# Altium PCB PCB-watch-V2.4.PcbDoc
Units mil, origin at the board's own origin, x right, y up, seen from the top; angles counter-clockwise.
Board outline 1043.31 x 1259.84 mil, 4 copper layers (Top Layer, GND, POWER, Bottom Layer), stack 23.756 mil thick; 96 components, 97 nets, 405 pads, 178 vias.
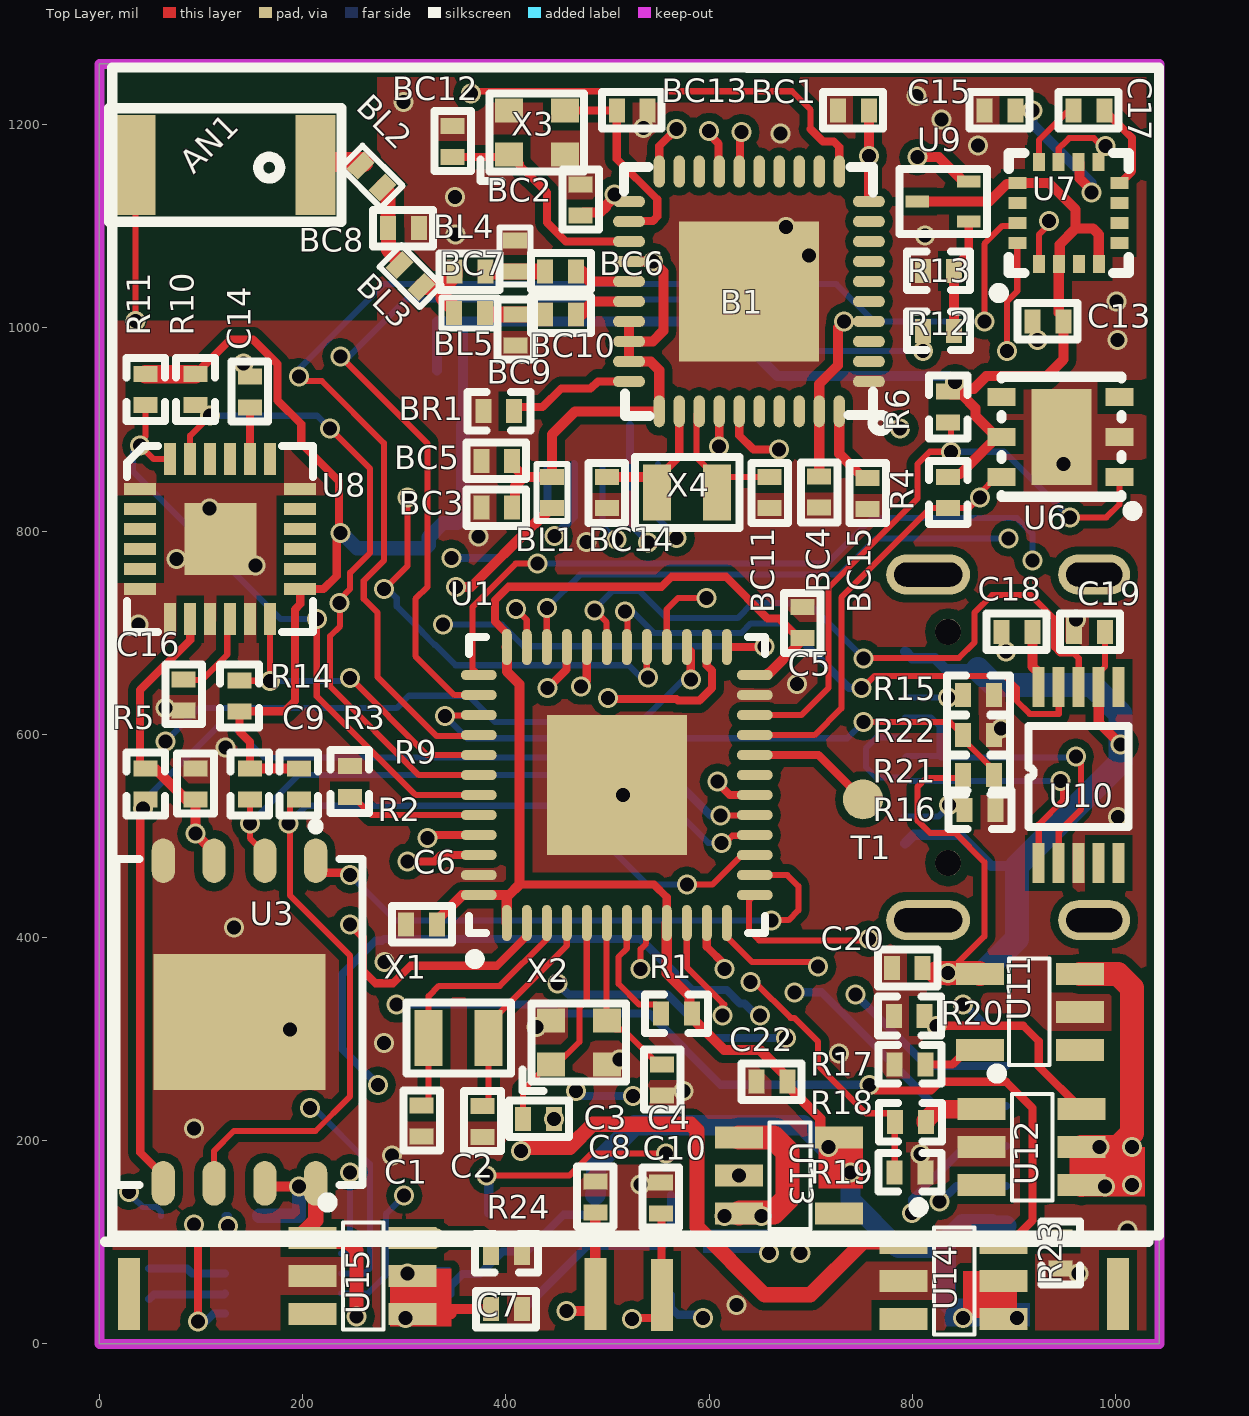
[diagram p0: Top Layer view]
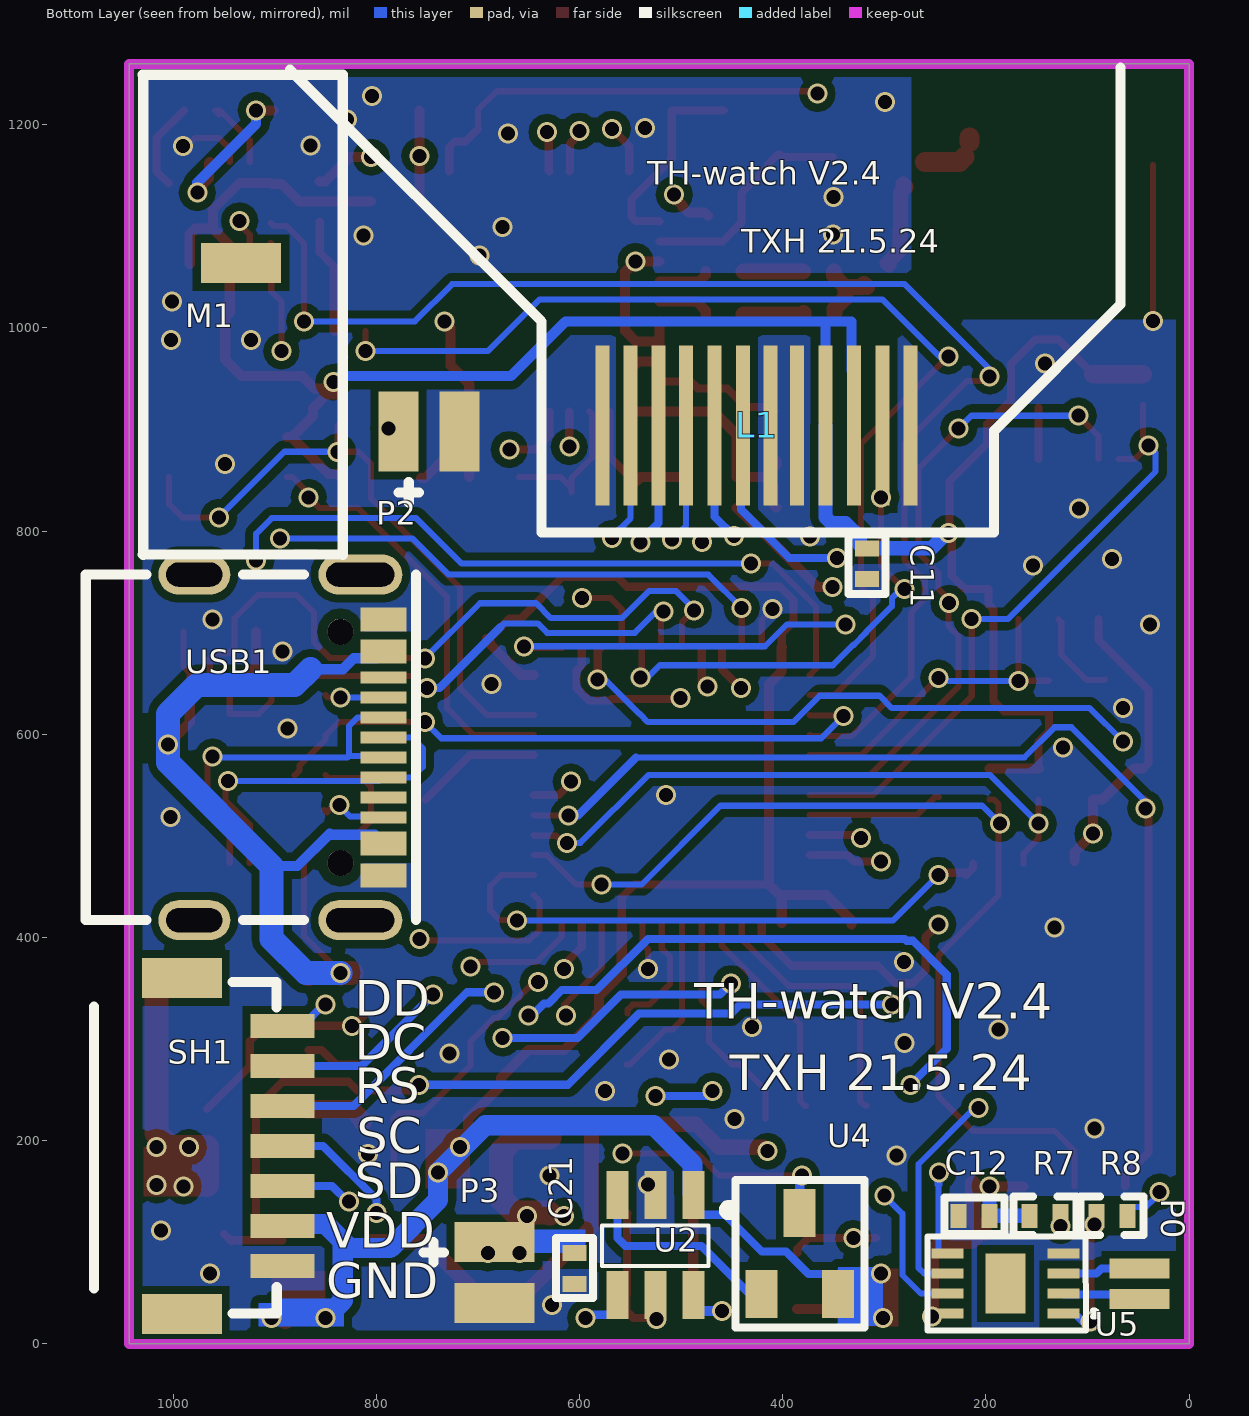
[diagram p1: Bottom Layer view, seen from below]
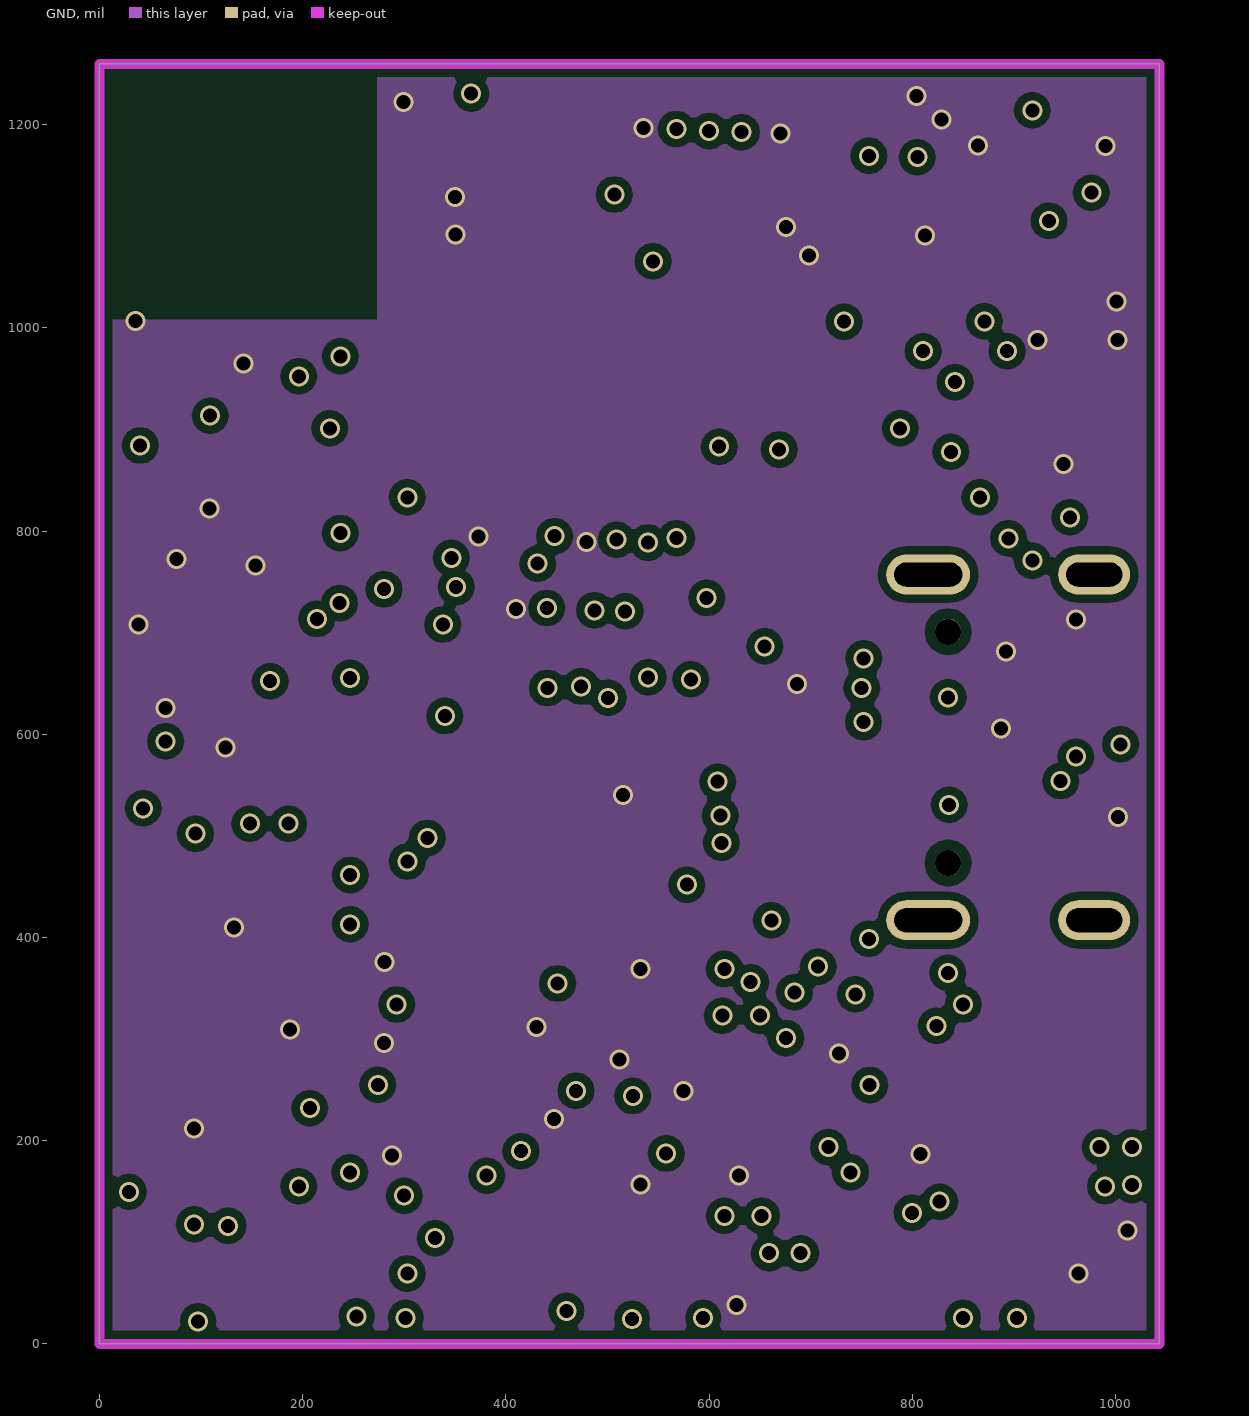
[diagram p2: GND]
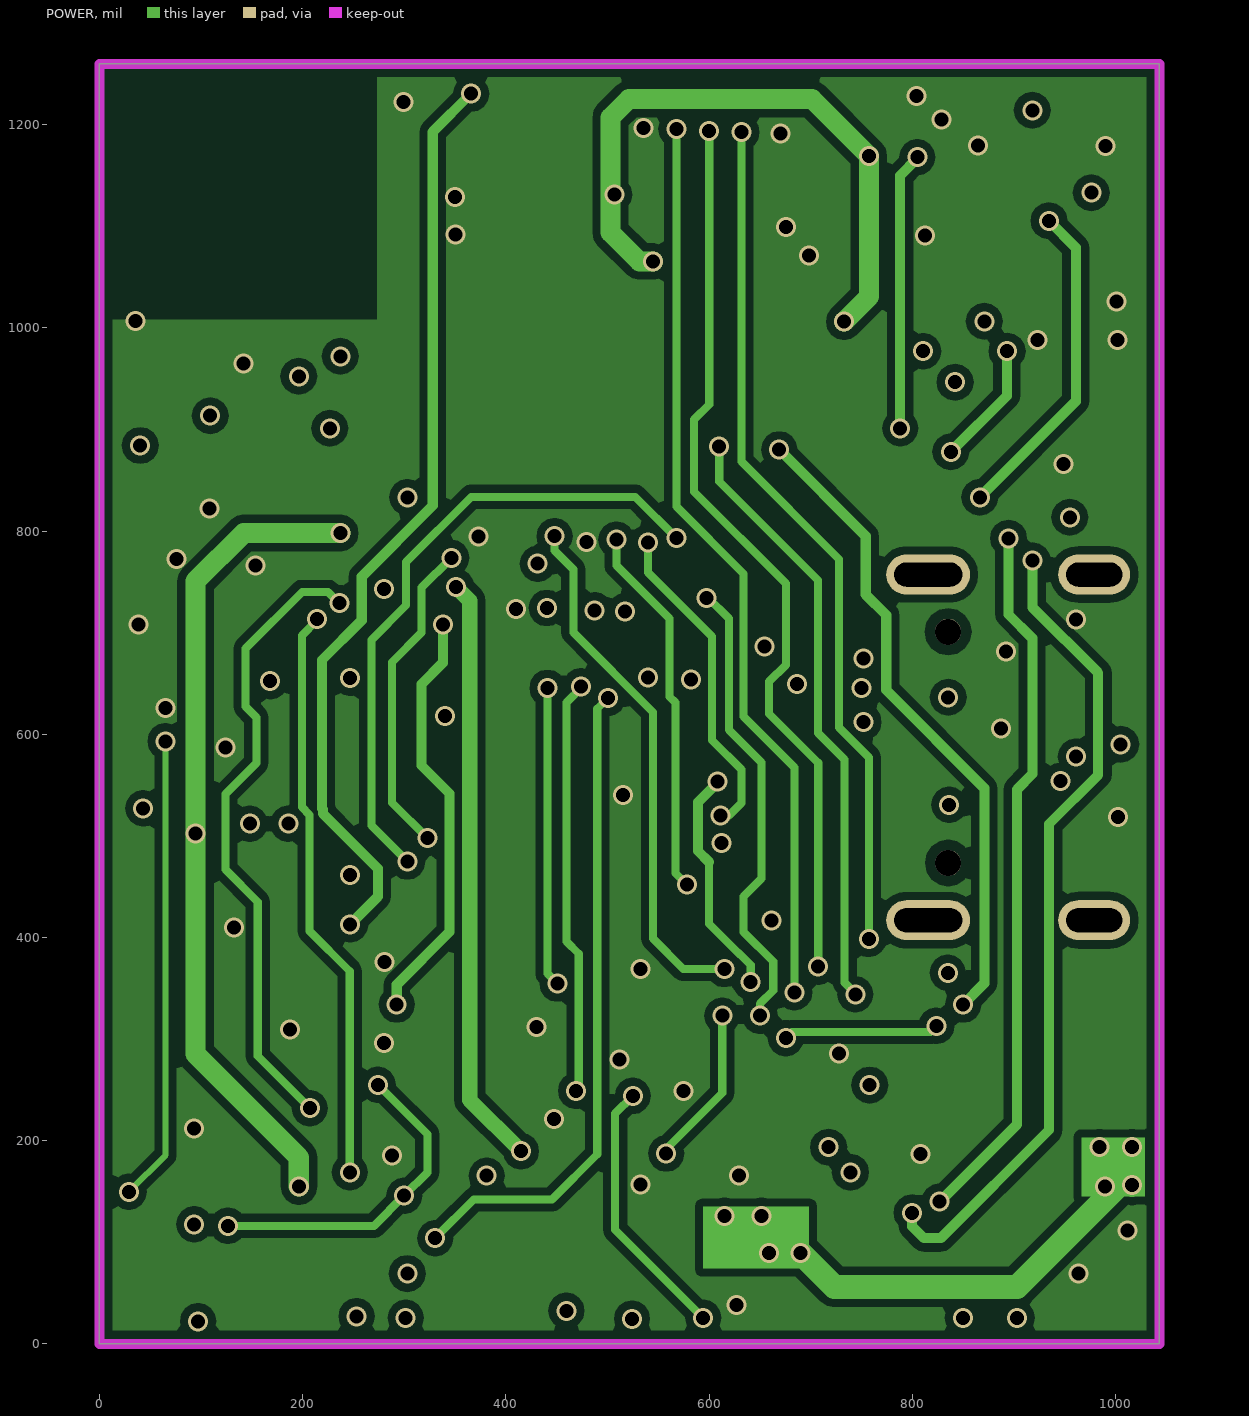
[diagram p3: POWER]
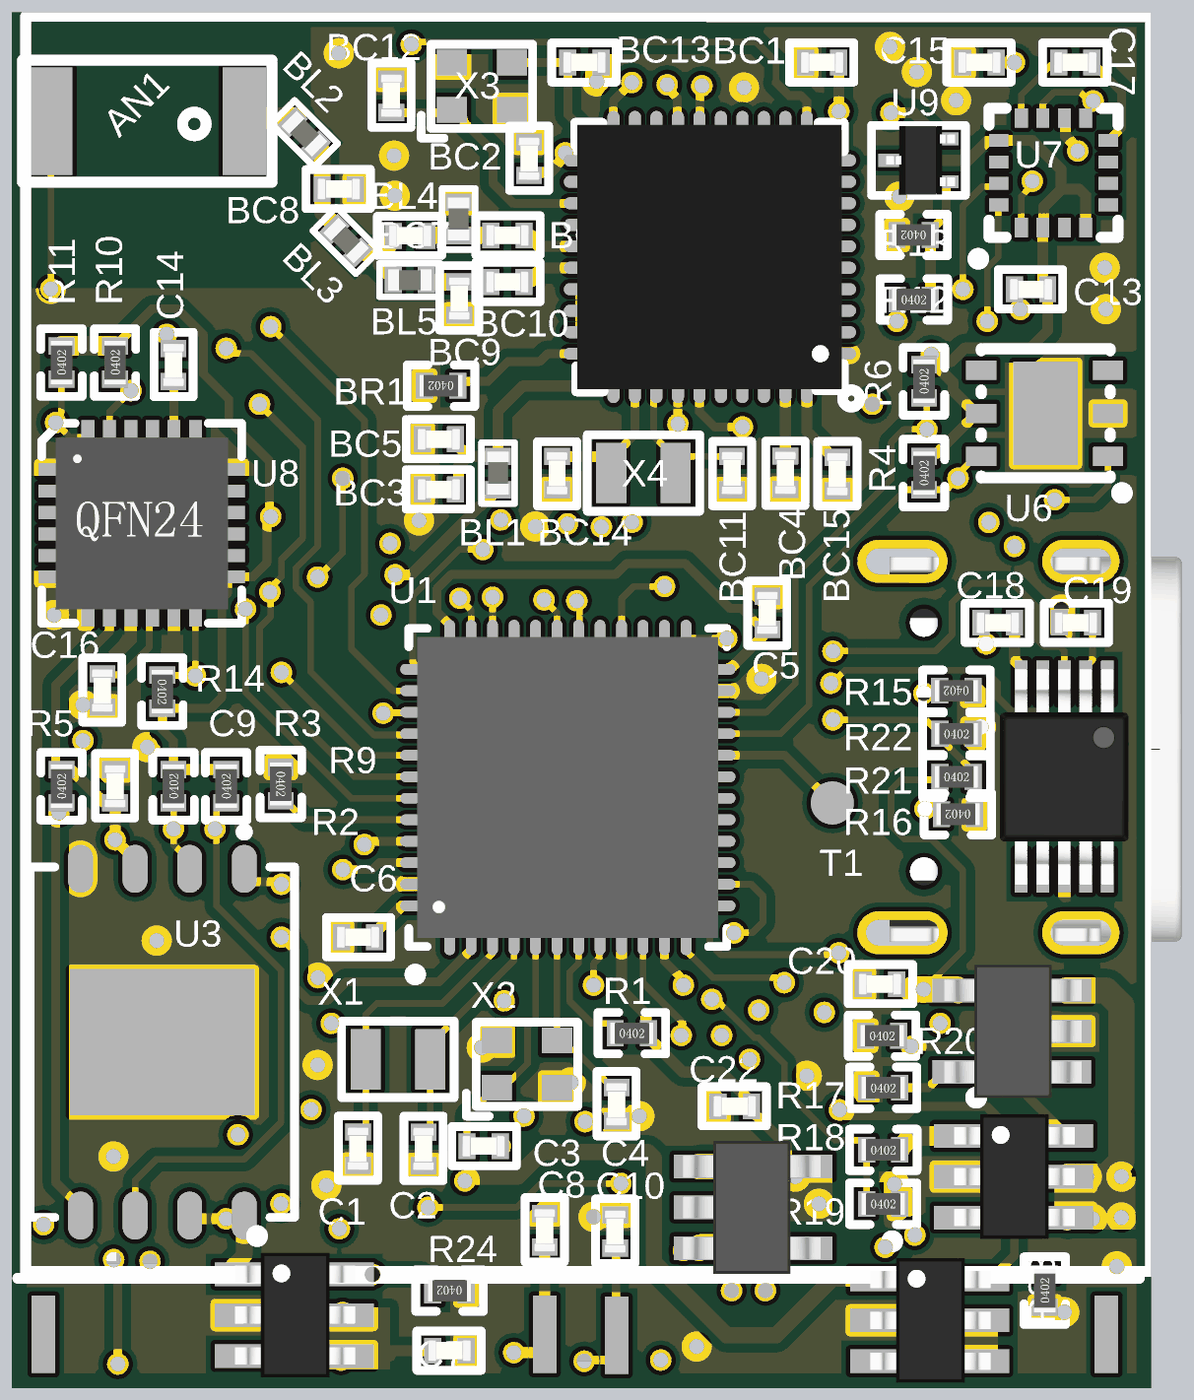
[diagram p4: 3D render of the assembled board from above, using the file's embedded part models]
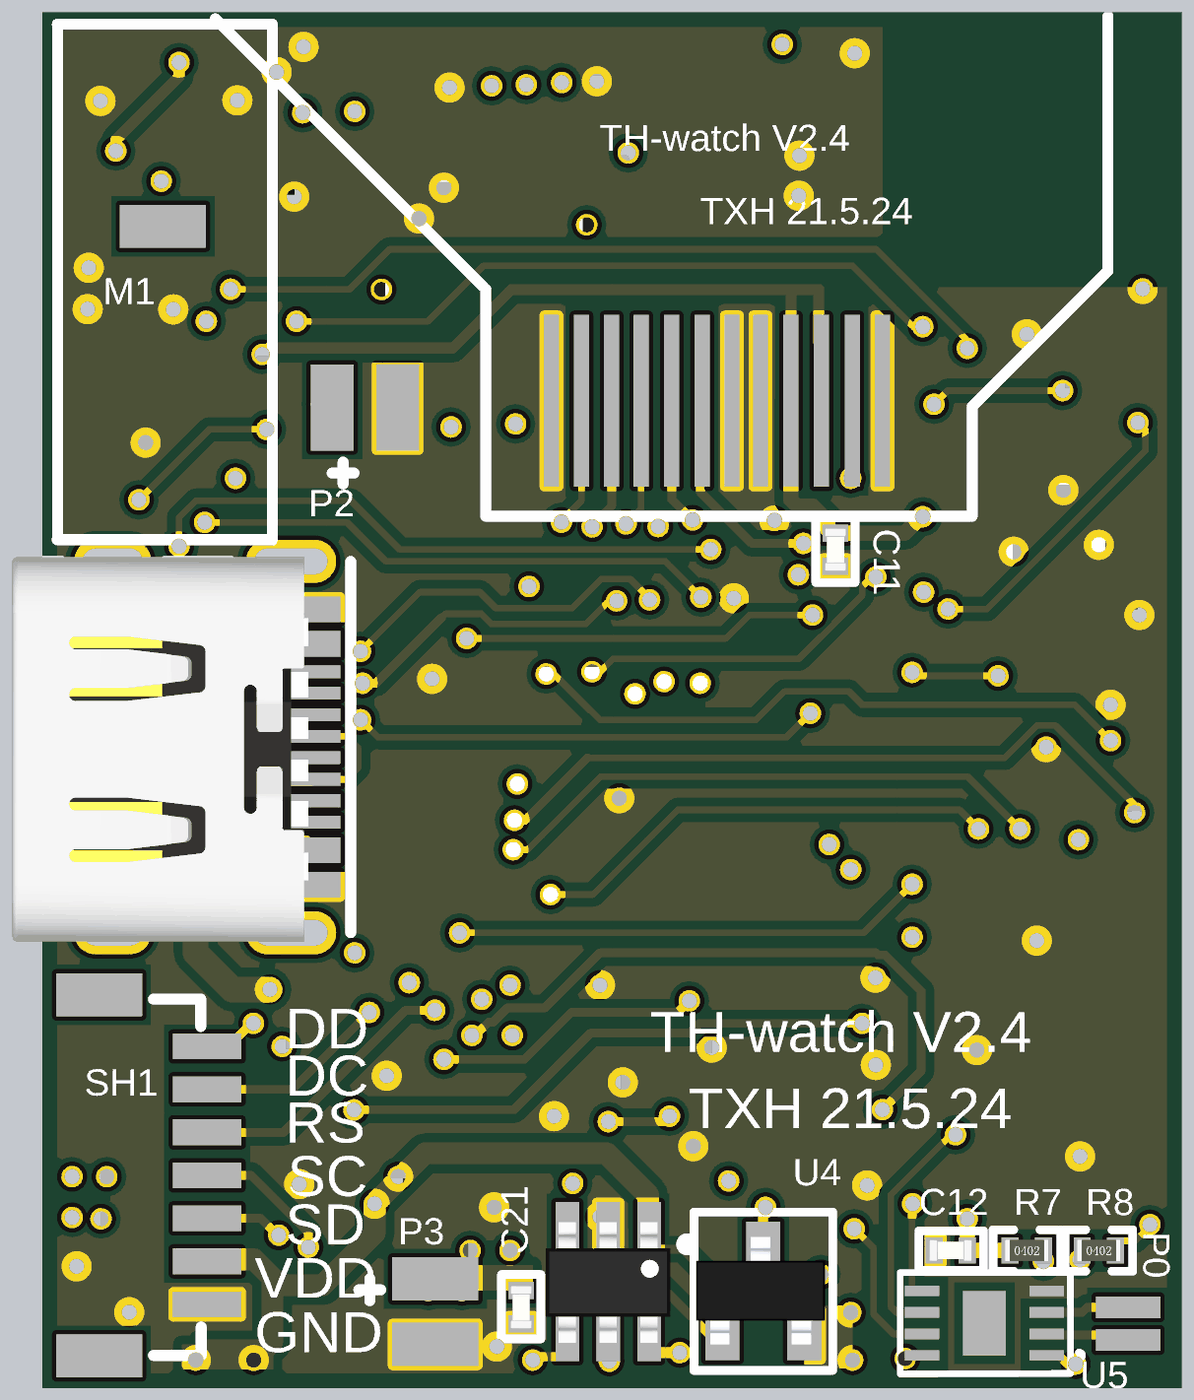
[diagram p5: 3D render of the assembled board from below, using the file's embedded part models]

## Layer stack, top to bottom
Top Solder: solder mask 0.4, Solder Resist, Dk 3.5
Top Layer: signal copper 1.4
Dielectric 2: prepreg 2.8, PP-006, Dk 4.1
GND: signal copper 1.378
Dielectric 1: dielectric 12.6, FR-4, Dk 4.8
POWER: signal copper 1.378
Dielectric 3: prepreg 2.8, PP-006, Dk 4.1
Bottom Layer: signal copper 1.4
Bottom Solder: solder mask 0.4, Solder Resist, Dk 3.5

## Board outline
0,0 0,1259.84 1043.31,1259.84 1043.31,0

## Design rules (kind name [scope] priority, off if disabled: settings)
Clearance [All] p1: gap=8 ignorepadtopadclearanceinfootprint=TRUE except(4: Arc-Arc Arc-Track Arc-SMDPad Arc-THPad Arc-Via Track-Track Track-SMDPad Track-THPad Track-Via SMDPad-SMDPad SMDPad-THPad SMDPad-Via THPad-THPad THPad-Via Via-Via; 10: Arc-Text Arc-Hole Track-Text Track-Hole SMDPad-Text SMDPad-Hole THPad-Text THPad-Hole Via-Text Via-Hole Fill-Text Fill-Hole Poly-Text Poly-Hole Region-Text Region-Hole Text-Text Text-Hole)
DiffPairsRouting [All] p1: maxlimit=10 minlimit=5.91 mostfreqgap=10 toplayer_minwidth=15 toplayer_maxwidth=15 toplayer_prefwidth=15 midlayer1_minwidth=15 midlayer1_maxwidth=15 midlayer1_prefwidth=15 midlayer2_minwidth=15 midlayer2_maxwidth=15 midlayer2_prefwidth=15 bottomlayer_minwidth=15 bottomlayer_maxwidth=15 bottomlayer_prefwidth=15 maxuncoupledlength=500
HoleToHoleClearance [All] p1: gap=5.91 allowstackedmicrovias=TRUE
MinimumSolderMaskSliver [All] p1: minsoldermaskwidth=0.39
PlaneConnect [All] p1: planeconnectstyle=Relief reliefexpansion=20 reliefentries=4 reliefconductorwidth=19.68 reliefairgap=10
PolygonConnect [All] p1: connectstyle=Direct reliefconductorwidth=15.75 reliefentries=4 polygonreliefangle="90 Angle" airgapwidth=5.91
RoutingVias [All] p1: holewidth=118.11 width=118.11 viastyle="Through Hole" minholewidth=9.84 minwidth=13.78 maxholewidth=118.11 maxwidth=118.11
SilkToSilkClearance [All] p1: silktosilkclearance=0
SilkToSolderMaskClearance [IsPad] p1: minsilkscreentomaskgap=0 clearancetoexposedcopper=TRUE
SolderMaskExpansion [All] p1: expansion=4
Width [All] p1: maxlimit=39.37 minlimit=3 preferedwidth=6
24 further rules are at their usual default settings.

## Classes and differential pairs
component class 04-POWERV2.4: C18 C19 C20 C21 C22 P3 R15 R16 R17 R18 R19 R20 R21 R22 R23 R24 U10 U11 U12 U13 U14 USB1
component class 03-PeripheralPart-V2.4: 1 C7 C8 C9 C10 C11 C12 C13 C14 C15 C16 C17 L1 M1 P0 P2 R3 R4 R5 R6 R7 R8 R9 R10 R11 R12 R13 R14 U2 U3 U4 U5 U6 U7 U8 U9
component class 02-bluetooth-V2.4: AN1 B1 BC1 BC2 BC3 BC4 BC5 BC6 BC7 BC8 BC9 BC10 BC11 BC12 BC13 BC14 BC15 BL1 BL2 BL3 BL4 BL5 BR1 X3 X4
component class 01-MCU-V2.4: C1 C2 C3 C4 C5 C6 R1 R2 SH1 T1 U1 X1 X2

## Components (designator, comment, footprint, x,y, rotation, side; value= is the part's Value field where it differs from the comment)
AN1 "AN9520-245" AN-5120 212.79,1160.24 r180 top
B1 "CC2541" QFN40-CC254X 639.28,1035.84 r90 top
BC1 "100nF" CC1005-0402 742.09,1214 r180 top
BC2 "100nF" CC1005-0402 473.67,1125.87 r90 top
BC3 "220nF" CC1005-0402 391,823 r180 top
BC4 "100nF" CC1005-0402 708.43,838.24 r270 top
BC5 "10uF" CC1005-0402 391,869 r180 top
BC6 "18pF" CC1005-0402 453.87,1055.63 r0 top
BC7 "1pF" CC1005-0402 364.68,1055.2 r180 top
BC8 "1pF" CC1005-0402 299.34,1098.11 r180 top
BC9 "1pF" CC1005-0402 409.69,997.84 r90 top
BC10 "18pF" CC1005-0402 453.76,1013 r0 top
BC11 "15pF" CC1005-0402 659.56,838 r270 top
BC12 "27pF" CC1005-0402 347.56,1183.57 r90 top
BC13 "27pF" CC1005-0402 524.39,1214 r180 top
BC14 "15pF" CC1005-0402 499.32,837.83 r270 top
BC15 "100pF" CC1005-0402 756,836.96 r90 top
BL1 "2nH" Inductor-0402 445.24,838 r270 top
BL2 "1nH" Inductor-0402 267.87,1148.81 r315 top
BL3 "1nH" Inductor-0402 306.15,1050.96 r315 top
BL4 "2nH" Inductor-0402 409.11,1070.64 r270 top
BL5 "2nH" Inductor-0402 364.41,1014.72 r0 top
BR1 "56KR" CR1005-0402 393,918 r180 top
C1 "15pF" CC1005-0402 317,219.24 r90 top
C2 "15pF" CC1005-0402 377,219 r90 top
C3 "27pF" CC1005-0402 432,221.52 r0 top
C4 "27pF" CC1005-0402 553.81,259.88 r90 top
C5 "100nF" CC1005-0402 691.89,710.02 r270 top
C6 "100nF" CC1005-0402 317.01,412.91 r0 top
C7 "100NF" CC1005-0402 400.81,34.2 r180 top
C8 "1pF" CC1005-0402 488,144.46 r90 top
C9 "100nF" CC1005-0402 94.47,551.13 r90 top
C10 "1pF" CC1005-0402 552.54,143.34 r90 top
C11 "100nF" CC1005-0402 317.01,767.81 r270 bottom
C12 "100nF" CC1005-0402 211.51,126 r180 bottom
C13 "100nF" CC1005-0402 933.45,1006.31 r180 top
C14 "2.2uF" CC1005-0402 148,937 r90 top
C15 "4.7uF" CC1005-0402 886.2,1214 r180 top
C16 "100NF" CC1005-0402 82.79,638.83 r90 top
C17 "0.22uF" CC1005-0402 974,1214 r180 top
C18 "100nF" CC1005-0402 902.98,700.86 r180 top
C19 "100nF" CC1005-0402 974.51,700.86 r0 top
C20 "10uF" CC1005-0402 795.03,369.91 r0 top
C21 "10uF" CC1005-0402 604.89,74 r90 bottom
C22 "10uF" CC1005-0402 662,258 r180 top
L1 "TFT LED" LCD-1.3-(2) 274,904.07 r180 top locked
M1 "motor" motor 833,1249 r0 bottom
P0 "power" POWER2 49,74 r270 bottom
P2 "power" POWER-3.7V 793,848 r180 bottom
P3 "power" POWER-3.7V 733.57,115 r270 bottom
R1 "10K" CR1005-0402 567.78,325 r0 top
R2 "10K" CR1005-0402 246.34,553.31 r270 top
R3 "47K" CR1005-0402 148,551.13 r90 top
R4 "10K" CR1005-0402 835.3,838 r90 top
R5 "47K" CR1005-0402 45.39,551.13 r90 top
R6 "10K" CR1005-0402 835.3,922 r90 top
R7 "4.7K" CR1005-0402 141.72,126 r180 bottom
R8 "1K" CR1005-0402 75.78,126 r180 bottom
R9 "47K" CR1005-0402 196.27,551.13 r90 top
R10 "10K" CR1005-0402 94.47,939.22 r90 top
R11 "10K" CR1005-0402 45.39,939.22 r90 top
R12 "1K" CR1005-0402 826,997 r0 top
R13 "10K" CR1005-0402 825.86,1056 r180 top
R14 "10K" CR1005-0402 137.79,637.83 r270 top
R15 "1.5K" CR1005-0402 865,638.58 r180 top
R16 "1.5K" CR1005-0402 866.53,525.6 r180 top
R17 "2KR" CR1005-0402 797.97,275 r0 top
R18 "10K" CR1005-0402 798.03,218.13 r0 top
R19 "10K" CR1005-0402 797.97,168.73 r0 top
R20 "10K" CR1005-0402 797.03,322.72 r0 top
R21 "10K" CR1005-0402 865.14,559.84 r0 top
R22 "10K" CR1005-0402 865.14,599.21 r0 top
R23 "10K" CR1005-0402 946,89.24 r90 top
R24 "10K" CR1005-0402 400.81,89.24 r180 top
SH1 "SH1.0-7P" SH1.0-7P 925.65,234.18 r270 bottom
T1 "测试点" 测试点 751.44,535.86 r0 top
U1 "STM32L431CCU6" STM32-UFQFPN48_N 509.16,550 r90 top locked
U2 "BS812A-1" SOT23-6 522.81,96.65 r0 bottom
U3 "W25Q64JVEIQ" WSON-8_L8.0-W6.10-P1.27-TL-EP 137.79,316.73 r270 top
U4 "SI2305" SOT-23 420.57,49.15 r180 bottom
U5 "ST25DV04k" UFDFPN8 180.59,59.4 r0 bottom
U6 "SI7020" DFN-6 945.84,892.64 r90 top
U7 "HMC5883L" LPCC-16_L3.0-W3.0-P0.50-BL 954,1113 r0 top
U8 "MPU6050" "QFN24 - duplicate" 118.82,792.01 r0 top
U9 "MMBT3904TT1G" SOT-416 830.3,1124.43 r0 top
U10 "CH340E" MSOP-10 924.47,473.3 r90 top
U11 "TP4054" SOT23-5 964.95,364.33 r270 top
U12 "TPS22860" SOT23-6 918.22,196 r270 top
U13 "TPS709" SOT23-5 629.69,127.91 r90 top
U14 "TPS22860" SOT23-6 841.23,64.39 r270 top
U15 "TPS22860" SOT23-6 259.44,69.2 r270 top
USB1 "Tpye-c 16P" "TYPE-C 16P" 835.3,473.3 r270 bottom locked
X1 "32.768Khz" XTAL-2012 383.06,301 r180 top
X2 "32Mhz" XTAL-2016 444.2,275 r0 top
X3 "32Mhz" XTAL-2016 402.88,1170.69 r0 top
X4 "32.768Khz" XTAL-2012 548.94,838 r0 top

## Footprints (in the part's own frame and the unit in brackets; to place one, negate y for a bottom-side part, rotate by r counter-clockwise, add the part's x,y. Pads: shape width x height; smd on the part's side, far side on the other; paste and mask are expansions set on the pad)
AN-5120 [mm]
  rect 1x2.5 smd: 1(0,0) 2(4.5,0)
  silkscreen extent -0.65,-1.42 5.16,1.42, body extent -0.32,-1.03 4.77,1.03, height 1.2
CC1005-0402 [mm]
  rect 0.4x0.6 smd: 1(-0.387,0) 2(0.387,0)
  silkscreen extent -0.74,-0.46 0.76,0.46, body extent -0.5,-0.25 0.5,0.25, height 0.3
CR1005-0402 [mm]
  rect 0.4x0.6 smd: 1(-0.387,0) 2(0.387,0)
  silkscreen extent -0.79,-0.48 0.79,0.48, body extent -0.5,-0.25 0.5,0.25, height 0.35
DFN-6 [mm]
  rect 0.45x0.701 smd: 1(-1.001,-1.476) 2(0,-1.476) 3(1.001,-1.476) 4(1.001,1.476) 5(0,1.476) 6(-1.001,1.476)
  rect 2.4x1.5 smd: 7(0,-0.025)
  silkscreen extent -1.95,-1.9 1.5,1.47, body extent -1.52,-1.55 1.5,1.47, height 1
Inductor-0402 [mm]
  rect 0.4x0.6 smd: 1(-0.387,0) 2(0.387,0)
  silkscreen extent -0.71,-0.39 0.71,0.39, body extent -0.5,-0.25 0.5,0.25, height 0.25
LCD-1.3-(2) [mm]
  rect 0.35x4 smd far side: 1(0,0) 2(-0.7,0) 3(-1.419,0) 4(-2.128,0) 5(-2.838,0) 6(-3.5,0) 7(-4.193,0) 8(-4.902,0) 9(-5.612,0) 10(-6.3,0) 11(-7,0) 12(-7.7,0)
  silkscreen extent -19.53,-8.94 6.64,20.25, body extent -19.52,-8.94 6.67,20.21, height 2.32
LPCC-16_L3.0-W3.0-P0.50-BL [mm]
  rect 0.3x0.45 smd: 1(-0.749,-1.275) 2(-0.249,-1.275) 3(0.251,-1.275) 4(0.751,-1.275) 9(0.75,1.275) 10(0.25,1.275) 11(-0.25,1.275) 12(-0.749,1.275)
  rect 0.45x0.3 smd: 5(1.275,-0.748) 6(1.275,-0.248) 7(1.275,0.252) 8(1.275,0.752) 13(-1.275,0.752) 14(-1.275,0.252) 15(-1.275,-0.248) 16(-1.275,-0.748)
  silkscreen extent -1.87,-2.12 1.5,1.5, body extent -1.42,-1.48 1.42,1.42, height 0.9
motor [mm]
  rect 2x1 smd: 3(2.54,4.699)
  silkscreen extent 0,0 5,12, body extent 0,0.03 4.95,11.96, height 4.9
MSOP-10 [mm]
  rect 1x0.3 smd: 1(0,0) 2(0,-0.5) 3(0,-1) 4(0,-1.5) 5(0,-2) 6(4.403,-2) 7(4.403,-1.5) 8(4.403,-1) 9(4.403,-0.5) 10(4.403,0)
  silkscreen extent 0.9,-2.25 3.42,0.25, body extent -0.32,-2.5 4.71,0.5, height 1.05
POWER2 [mm]
  rect 0.5x1.5 smd: 1(0,0) 2(0.762,0)
POWER-3.7V [mm]
  rect 1x2 smd: 1(0.381,1.27) 2(1.905,1.27)
  silkscreen extent 0.38,-0.51 0.89,0
"QFN24 - duplicate" [mm]
  rect 0.8x0.3 smd: 1(-2,1.25) 2(-2,0.75) 3(-2,0.25) 4(-2,-0.25) 5(-2,-0.75) 6(-2,-1.25) 13(2,-1.25) 14(2,-0.75) 15(2,-0.25) 16(2,0.25) 17(2,0.75) 18(2,1.25)
  rect 1.8x1.8 smd: 1(0.005,0)
  rect 0.3x0.8 smd: 7(-1.25,-2) 8(-0.75,-2) 9(-0.25,-2) 10(0.25,-2) 11(0.75,-2) 12(1.25,-2) 19(1.25,2) 20(0.75,2) 21(0.25,2) 22(-0.25,2) 23(-0.75,2) 24(-1.25,2)
  silkscreen extent -2.32,-2.32 2.32,2.32, body extent -2,-2 2.01,2, height 0.9
QFN40-CC254X [mm]
  oval 0.28x0.8 smd: 1(-2.25,-2.998) 2(-1.75,-2.998) 3(-1.25,-2.998) 4(-0.75,-2.998) 5(-0.25,-2.998) 6(0.25,-2.998) 7(0.75,-2.998) 8(1.25,-2.998) 9(1.75,-2.998) 10(2.25,-2.998) 21(2.246,2.996) 22(1.75,2.998) 23(1.25,2.998) 24(0.75,2.998) 25(0.25,2.998) 26(-0.25,2.998) 27(-0.75,2.998) 28(-1.25,2.998) 29(-1.75,2.998) 30(-2.25,2.998)
  oval 0.8x0.28 smd: 11(2.998,-2.256) 12(2.998,-1.756) 13(2.998,-1.256) 14(2.998,-0.756) 15(2.998,-0.256) 16(2.998,0.244) 17(2.998,0.744) 18(2.998,1.244) 19(2.998,1.744) 20(2.998,2.244) 31(-2.998,2.244) 32(-2.998,1.744) 33(-2.998,1.244) 34(-2.998,0.744) 35(-2.998,0.244) 36(-2.998,-0.256) 37(-2.998,-0.756) 38(-2.998,-1.256) 39(-2.998,-1.756) 40(-2.998,-2.256)
  rect 3.5x3.5 smd: 41(0,0)
  silkscreen extent -3.49,-3.49 3.11,3.12, body extent -3.08,-3.07 3.07,3.08, height 1.08
SH1.0-7P [mm]
  rect 0.6x1.6 smd: 1(-2,0.844) 2(-1,0.844) 3(0,0.844) 4(1,0.844) 5(2,0.844) 6(3,0.844) 7(4,0.844)
  rect 1x2 smd: 8(-3.2,-1.67) 9(5.2,-1.67)
  silkscreen extent -3.1,-3.87 5.19,0.7, body extent -3.15,-3.89 5.18,0.69, height 3
SOT23-5 [mm] "适用于MIC5205"
  rect 0.55x1.2 smd: 1(1.905,0) 2(0.955,0) 3(0.005,0) 4(0.005,-2.5) 5(1.905,-2.5)
  silkscreen extent -0.38,-1.78 2.29,-0.76, body extent -0.6,-2.82 2.5,0.38, height 1.45
SOT23-6 [mm]
  rect 0.55x1.2 smd: 1(-0.889,-1.27) 2(0.061,-1.27) 3(1.011,-1.27) 4(1.011,1.23) 5(0.061,1.23) 6(-0.889,1.23)
  silkscreen extent -1.9,-1.02 1.4,0.51, body extent -1.39,-1.4 1.51,1.4, height 1.45
SOT-23 [mm]
  rect 0.8x1.2 smd: 1(0,0) 2(1.905,0) 3(0.95,2.02)
  silkscreen extent -0.66,-0.84 2.57,2.84, body extent -0.61,-0.23 2.39,2.27, height 1.05
SOT-416 [mm]
  rect 0.585x0.301 smd: 1(0.642,-0.5) 2(0.642,0.5) 3(-0.642,0)
  silkscreen extent -1.09,-0.81 1.09,0.81, body extent -0.75,-0.8 0.85,0.8, height 0.78
STM32-UFQFPN48_N [mm] "QFN, 48-Leads, Body 7.1x7.1mm, Pitch 0.5mm, Thermal Pad 5.6x5.6mm, IPC Medium Density"
  oval 0.9x0.25 smd: 1(-3.45,2.75) 2(-3.45,2.25) 3(-3.45,1.75) 4(-3.45,1.25) 5(-3.45,0.75) 6(-3.45,0.25) 7(-3.45,-0.25) 8(-3.45,-0.75) 9(-3.45,-1.25) 10(-3.45,-1.75) 11(-3.45,-2.25) 12(-3.45,-2.75) 25(3.45,-2.75) 26(3.45,-2.25) 27(3.45,-1.75) 28(3.45,-1.25) 29(3.45,-0.75) 30(3.45,-0.25) 31(3.45,0.25) 32(3.45,0.75) 33(3.45,1.25) 34(3.45,1.75) 35(3.45,2.25) 36(3.45,2.75)
  oval 0.25x0.9 smd: 13(-2.75,-3.45) 14(-2.25,-3.45) 15(-1.75,-3.45) 16(-1.25,-3.45) 17(-0.75,-3.45) 18(-0.25,-3.45) 19(0.25,-3.45) 20(0.75,-3.45) 21(1.25,-3.45) 22(1.75,-3.45) 23(2.25,-3.45) 24(2.75,-3.45) 37(2.75,3.45) 38(2.25,3.45) 39(1.75,3.45) 40(1.25,3.45) 41(0.75,3.45) 42(0.25,3.45) 43(-0.25,3.45) 44(-0.75,3.45) 45(-1.25,3.45) 46(-1.75,3.45) 47(-2.25,3.45) 48(-2.75,3.45)
  rect 3.5x3.5 smd: 49(0,0)
  silkscreen extent -4.47,-3.7 3.7,3.7, body extent -3.5,-3.5 3.5,3.5, height 0.55
"TYPE-C 16P" [mm]
  oval 1x2.099 hole 0.6 slot 1.7 at 90 deg: 1(-7.21,0.5) 2(1.43,0.5)
  oval 1x1.799 hole 0.6 slot 1.4 at 90 deg: 3(-7.21,-3.65) 4(1.43,-3.65)
  rect 0.6x1.15 smd: A1B12(-6.09,1.075) A4B9(-5.29,1.075) B1A12(0.31,1.075) B4A9(-0.49,1.075)
  rect 0.3x1.15 smd: A5(-4.14,1.075) A6(-3.14,1.075) A7(-2.64,1.075) A8(-1.64,1.075) B5(-1.14,1.075) B6(-2.14,1.075) B7(-3.64,1.075) B8(-4.64,1.075)
  round 0.65 hole 0.65 unplated: ""(-5.78,0) ""(0,0)
  silkscreen extent -7.21,-6.37 1.43,1.89, body extent -7.31,-6 1.63,0.9, height 3.18
UFDFPN8 [mm]
  rect 0.805x0.249 smd paste+0 mask+0: 1(-1.452,0.751) 2(-1.452,0.25) 3(-1.452,-0.25) 4(-1.452,-0.751) 5(1.452,-0.751) 6(1.452,-0.25) 7(1.452,0.25) 8(1.452,0.751)
  rect 1x1.5 smd paste+0 mask+0: 9(0,0)
  silkscreen extent -2.28,-1.18 1.96,1.18, body extent -1.52,-1.14 1.52,1.14, height 1
WSON-8_L8.0-W6.10-P1.27-TL-EP [mm]
  oval 1.115x0.581 smd: 1(-4.033,1.905) 2(-4.033,0.635) 3(-4.033,-0.635) 4(-4.033,-1.905) 5(4.033,-1.905) 6(4.033,-0.635) 7(4.033,0.635) 8(4.033,1.905)
  rect 3.4x4.3 smd: 4(0,0)
  silkscreen extent -4.99,-3.08 4.08,3.08, body extent -4.06,-3.1 4.06,3.1, height 1.2
XTAL-2012 [mm]
  rect 0.7x1.4 smd: 1(0,0) 2(1.5,0)
  silkscreen extent -0.56,-0.89 2.06,0.89, body extent -0.21,-0.69 1.76,0.69, height 0.55
XTAL-2016 [mm] "缺的角在右边"
  rect 0.7x0.6 smd: 1(0,0) 2(1.4,0) 3(1.4,1.1) 4(0,1.1)
  silkscreen extent -0.71,-0.66 1.88,1.52, body extent -0.27,-0.24 1.69,1.4, height 0.55
测试点 [mm]
  round 1 smd: 1(0,0)

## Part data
AN1: "2.4G全向天线 蓝牙天线 陶瓷贴片 WIFI内置"
B1: "低功耗蓝牙芯片"
BC1 BC2 BC3 BC4 BC5 BC6 BC7 BC8 BC9 BC10 BC11 BC12 BC13 BC14 BC15 C1 C2 C3 C4 C5 C6 C7 C8 C9 C10 C11 C12 C13 C14 C15 C16 C17 C18 C19 C20 C21 C22: library part "Chip capacitor", "贴片电容"
BL1 BL2 BL3 BL4 BL5: library part Inductor-0402, "0402封装的电感"
BR1 R1 R2 R3 R4 R5 R6 R7 R8 R9 R10 R11 R12 R13 R14 R15 R16 R17 R18 R19 R20 R21 R22 R23 R24: library part "Chip resistor", "贴片电阻"
L1: library part LCD-IPSscreen-1.3, "1.3寸显示屏幕"
M1: "震动马达"
SH1: "间距为1mm的端子"
U1: "stm32低功耗单片机 主频80MHz"
U2: "触摸按键 两路 SOP23-6封装极简电路"
U3: library part W25Q256JVEIQ, "FLASH"
U4: "PMOS场效应MOS管 SOT-23"
U5: "NFC芯片4K存储空间"
U6: "温湿度传感器芯片"
U7: "三轴罗盘"
U8: "陀螺仪"
U9: "NPN 电流 - 集电极（Ic）（最大值）：200mA 电压 - 集射极击穿（最大值）：40V SOT-23-3"
U10: "usd转串口芯片 MSOP10封装"
U11: "迷你充电IC SOT-23-5"
U12 U14 U15: "超低泄漏电流负载开关  超低泄漏电流负载开关 它可支持最大 200mA 的持续电 流。 此开关可由一个打开/关闭"
U13: "3.3V降压IC SOT23-5封装 最大输出150ma电流"
USB1: "16P 封装的TYPE -c接口 4固定插脚 双向"
X1 X4: library part "XTAL 2012", "2012封装的时钟晶振"
X2 X3: library part "XTAL 2016", "2016封装的晶振"

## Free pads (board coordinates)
  rect 21.65x70.87 smd: 2(28.95,49.15) 2(488,49.15) 2(553.81,48.22) 2(1002.53,49.15)

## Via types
v1: diameter 19.68, hole 13.78, Top Layer to Bottom Layer, 178 vias

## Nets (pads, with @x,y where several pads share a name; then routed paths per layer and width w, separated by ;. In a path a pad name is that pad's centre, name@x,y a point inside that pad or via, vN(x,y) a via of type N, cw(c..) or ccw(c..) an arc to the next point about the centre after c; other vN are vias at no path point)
3.3V: C9.1 C11.1 C12.2 C13.1 L1.3 L1.4 R3.2 R4.2 R5.2 R6.2 R7.1 R9.2 R10.2 R11.2 R14.2 U3.3 U3.7 U3.8 U5.8 U6.5 U7.2 U7.4 U7.13 U8.8 U8.13 U9.3 U15.1 | length 3673.1
  Top Layer w8: R5.2 40,571.76 40,643.54 89.29,692.83 U8.8 ; R10.2 128.66,988.65 151.13,988.65 175.39,964.39 175.39,928.61 198.61,905.39 198.61,886.11 235.76,848.96 235.76,799.24 v1(237,798) 233.53,794.53 233.53,755.77 220.55,742.79 U8.13 197.56,728.09 192.29,722.82 192.29,632.77 182.11,622.59 R14.2 137.79,602.76 148,592.54 R3.2
  Top Layer w10: R5.2 54.34,566.37 84.81,535.9 C9.1 v1(94.47,502.12) 112.79,483.8 U3.3 ; R3.2 R9.2 ; U3.7@162.79,154.98 U3.8@212.79,154.98 ; U9.3 876.01,1124.43 893.28,1141.7 902.9,1141.7 U7.13 934.55,1142.61 960.74,1116.42 960.74,1098.11 960.97,1097.88 ; R4.2 838.18,856.11 847.07,856.11 863,872.05 883.2,892.24 U6.5@882.8,892.64 ; v1(842.11,946.61) R6.2@842.11,940.11 ; U6.5 U6.5@882.8,892.64 ; U7.4 983.59,1092.02 977.73,1097.88 960.97,1097.88 ; R6.2@842.11,940.11 860.43,940.11 872.79,952.47 932.49,952.47 948.69,968.67 C13.1 948.69,1010.25 944.22,1014.72 U7.2 945.12,1063.72 945.12,1082.02 960.97,1097.88 ; R6.2@842.11,940.11 839.24,937.24 R6.2 838.18,934.36 848.59,934.36 862.11,920.85 862.11,913.33 U6.5@882.8,892.64
  Top Layer w14: U15.1 213.27,100.37 244.43,100.37 253,91.8 v1(253,27)
  Top Layer w15: U15.1@200.27,109 212.79,121.51 212.79,154.98 U3.8
  Top Layer w18: R11.2 R10.2
  POWER w20: v1(196.27,154.98) 196.27,183.48 94.47,285.28 v1(94.47,502.12) 94.47,750.47 142,798 v1(237,798)
  Bottom Layer w10: L1.3@332.24,957.97 332.24,1006.12 357.8,1006.12 ; L1.4 357.8,1006.12 ; v1(842.11,946.61) 836.25,952.47 667.53,952.47 613.88,1006.12 357.8,1006.12
  Bottom Layer w14: R7.1 C12.2 v1(196.27,154.98) ; v1(237,798) 238.54,798 253.49,783.04 C11.1 320.95,783.04 324.11,786.21 324.11,793.9 338.1,807.89 352.22,807.89 357.8,813.47 L1.4
5V: C19.2 C20.2 R21.1 U10.7 U11.4 USB1.A4B9 USB1.B4A9 | length 1165.4
  Top Layer w6: v1(834.99,365.12) 870.96,401.09 870.96,474.12 842.25,502.82 817.26,502.82 805.25,514.84 805.25,548.29 813.98,557.02 847.08,557.02 R21.1 ; U10.7 983.52,660.42 989.75,666.65 C19.2
  Top Layer w10: U10.7 983.52,611.47 v1(1005,590)
  Top Layer w23.62: 824.45,365.12 v1(834.99,365.12) ; v1@834.99,364.54 v1(834.99,365.12) ; U11.4 865.54,365.12 v1(834.99,365.12)
  Bottom Layer w10: USB1.B4A9 801.48,501.09 846.82,501.09 ; USB1.A4B9 799.79,674.76 822.1,674.76 832.85,664 864.78,664 ; 845.79,502.12 846.82,501.09 ; 903,470.41 877.5,470.41 846.82,501.09
  Bottom Layer w23.62: v1@835.28,364.83 869.14,364.83 903,398.68 903,470.41 1005,572.41 v1(1005,590) 1005,620.14 976.65,648.48 880.3,648.48 864.78,664
ADC1_IN15: R18.1 R19.1 U1.18 | length 535.6
  Top Layer w6: v1(641,356) 645.13,356 680.24,320.89 683.84,320.89 707.39,297.34 707.39,273.82 754.27,226.94 777.92,226.94 782.8,222.07 R18.1 ; R19.1@782.76,168.77 R18.1
  Top Layer w8: v1@610,554 610,550.54 620.39,540.16 U1.18
  POWER w8: 600.05,474.11 600.05,413.49 629.6,383.94 630.06,383.94 641,373 v1(641,356)
  POWER w10: 600.05,474.11 589.11,485.05 589.11,533.11 v1@610,554
  other v1: 608.39,553.26
BLE_ON: R23.2 U1.25 U14.6 | length 1646.4
  Top Layer w8: U1.25 654.01,685.83 v1(654.75,686.56) ; v1@763.08,249.33 818.53,249.33 827.2,258 892.44,258 918.22,232.22 918.22,121.51 U14.6@900.9,104.2 ; U14.6@892.19,101.93 943.46,101.93 R23.2 ; R23.2@942.62,100.88 R23.2@949.59,107.84
  POWER w10: v1(292.55,334) 292.55,353.44 344.57,405.46 344.57,541.61 317.01,569.17 317.01,649.29 338,670.29 v1(338,708)
  Bottom Layer w6: v1(338,708) 395.91,708 417.35,686.56 v1(654.75,686.56)
  Bottom Layer w8: v1(292.55,334) 441.95,334 450.95,325 541.3,325 611.3,255 v1@758,255
  other v1: 758,254.71
BOOT0: R2.2 U1.44 | length 134.3
  Top Layer w6: R2.2 250.27,538.07 267.87,520.47 U1.44
DEBUG_CLOCK: B1.34 SH1.2 | length 808.3
  Top Layer w8: v1(610,883) B1.34
  POWER w8: v1(610,883) 610,848.89 707.34,751.55 707.34,601.33 733.38,575.29 733.38,355.46 744,344.84 v1(744,344)
  Bottom Layer w8: v1@743,345 v1(744,344) 814.45,273.55 SH1.2
DEBUG_DATA: B1.35 SH1.1 | length 758.3
  Top Layer w8: B1.35 629.69,894.11 643.59,880.21 v1(669.06,880.21)
  POWER w10: v1(669.06,880.21) 754.27,795.01 754.27,737.38 774.37,717.28 774.37,643.51 870.96,546.92 870.96,354.85 v1(850.11,334)
  Bottom Layer w8: v1(850.11,334) 851.66,334 872.75,312.92 SH1.1
DM_USB-: U10.2 USB1.A7 USB1.B7 | length 360.9
  Top Layer w6: U10.2 944.15,504.16 965.89,525.89 965.89,582.11 961.78,578 v1(961,578)
  Bottom Layer w6: USB1.A7 794.13,578.38 827,578.38 ; USB1.B7 818.27,616.61 827,607.87 827,578.38 ; v1(961,578) 960.11,577.11 828.27,577.11 827,578.38
DOUP: B1.40 BC15.2 | length 79.5
  Top Layer w10: B1.40 728.12,876.14 752.06,852.2 BC15.2
DP_USB+: U10.1 USB1.A6 USB1.B6 | length 351.4
  Top Layer w6: U10.1 924.47,511.12 948.36,535.01 948.36,551.68 946.78,553.25 v1@946,553.25
  Bottom Layer w6: USB1.A6 792.06,596 791.14,596.92 765.05,596.92 754.27,586.14 754.27,567.76 764.47,557.55 USB1.B6 793.43,558 797.43,554 v1(946,554)
GET_VBAT: R20.2 U1.33 U12.6 | length 953.5
  Top Layer w8: v1(440.95,645.5) 441.5,645.5 459.59,663.59 459.59,685.47 U1.33 ; R20.2 821.88,313.11 909.21,313.11 924.52,297.79 924.52,273.12 U12.6
  POWER w8: v1@443.15,643.3 v1(440.95,645.5) 440.95,364.54 v1(450.84,354.65) ; v1(675.6,301) 681.49,306.89 817.78,306.89 v1(823.81,312.92)
  Bottom Layer w8: v1(450.84,354.65) 461.49,344 559.06,344 602.06,301 v1(675.6,301)
GND: AN1.2 B1.1 B1.41 BC1.2 BC2.2 BC3.2 BC4.2 BC5.2 BC8.1 BC9.1 BC11.2 BC12.2 BC13.1 BC14.2 BC15.1 BL4.1 BR1.2 C1.1 C2.1 C3.2 C4.1 C5.1 C6.1 C7.1 C8.2 C9.2 C10.2 C11.2 C12.1 C13.2 C14.2 C15.2 C16.1 C18.2 C19.1 C20.1 C21.1 C22.2 L1.1 L1.5 L1.6 L1.12 P2.2 P3.2 R2.1 R13.2 R15.1 R16.1 R17.1 R19.2 R20.1 R22.2 R23.1 R24.1 SH1.7 U1.8 U1.23 U1.35 U1.47 U1.49 U2.2 U3.4 U5.4 U6.2 U6.7 U7.9 U7.11 U8.1 U8.6 U8.7 U8.9 U8.11 U8.18 U10.3 U11.2 U12.2 U13.2 U14.2 U15.2 USB1.A1B12 USB1.B1A12 X2.2 X2.4 X3.2 X3.4 | length 310
  Top Layer w6: v1(35.62,1006.67) AN1.2 ; v1(410.15,723.3) 410.15,722.96 420.57,712.54 U1.35 ; v1(532.68,369) 532.68,388.59 537.95,393.86 537.95,413.44 U1.8 ; U7.11 944.15,1176.62 947.67,1180.13 947.94,1180.13 954.5,1186.69 978.68,1186.69 986.56,1178.81 v1(990.26,1178.81)
  other v1: 627.15,38 963.84,69.43 1011.96,111.45 532.68,156.81 629.69,165.5 288,185.59 808.18,186.76 92.97,212.11 447.24,221.52 574.74,249 511.83,279.96 728,286 280.01,295.88 187.46,309.5 430.35,311.82 280.33,375.84 132.59,409.78 1002.31,518.77 515.03,540.16 124,587 887.42,605.49 65.01,625.74 686.45,649.5 892.43,681.57 38.62,708 961.14,713.06 153.72,765.94 75.78,772.26 479.38,789.02 372.88,794.53 108.26,822.36 948.86,865.91 141.72,965.1 923.49,987.87 1001.95,988.12 1000.97,1026 698.46,1071.09 812.75,1091.11 350.61,1092.02 675.6,1099.34 349.98,1128.7 864.78,1179.34 670.47,1191.04 535.55,1196.76 828.81,1205.28 299.34,1222.47 804.25,1228.31
HMC_DRDY: U1.40 U7.15 | length 1328.7
  Top Layer w6: v1(196.27,952.24) 200.98,947.53 219,947.53 280.01,886.52 280.01,770.92 260.12,751.03 260.12,733.24 273.44,719.92 273.44,656.43 331.76,598.11 372.23,598.11 U1.40 ; v1(870.96,1006.31) 870.96,1082.6 888.69,1100.33 900.9,1100.33 U7.15
  Bottom Layer w6: v1(196.27,952.24) 196.27,959.4 279.87,1043 725.3,1043 761.99,1006.31 v1(870.96,1006.31)
IIC1_SCL: R10.1 U1.42 U5.6 U8.23 | length 1482.5
  Top Layer w6: U8.23 89.29,893.83 v1(108.98,913.51) ; v1(226.76,901) 266.39,861.37 266.39,778.53 246.76,758.9 246.76,743.16 236.23,732.63 v1(236.23,728.93) 236.82,728.34 236.82,706.46 226.87,696.52 226.87,647.21 314.24,559.84 U1.42
  POWER w8: v1(207,232) 155.8,283.2 155.8,434.94 124,466.73 124,541.23 154.48,571.71 154.48,616.59 143.89,627.18 143.89,684.42 199.53,740.06 225.1,740.06 v1(236.23,728.93)
  Bottom Layer w6: v1(108.98,913.51) 214.25,913.51 v1(226.76,901) ; v1(207,232) 211.23,232 266.23,177 266.23,74.62 260.86,69.25 U5.6
IIC1_SDA: R11.1 U1.43 U5.5 U8.24 | length 1280.7
  Top Layer w6: R11.1 45.39,893.28 40,887.9 v1(40,884.19) 53.45,870.75 U8.24 ; v1(213.89,713.46) 213.89,637.35 311.08,540.16 U1.43
  POWER w8: v1(213.89,713.46) 213.89,711.94 199.2,697.26 199.2,528.34 206.89,520.65 206.89,406.14 246.34,366.69 v1(246.34,168.77)
  Bottom Layer w6: v1(40,884.19) 33.04,877.23 33.04,858.5 178.07,713.46 v1(213.89,713.46) ; U5.5 244.86,88.95 246.76,90.85 246.76,156.81
  Bottom Layer w8: v1(246.34,168.77) 246.76,168.34 246.76,156.81
IIC2_SCL: R4.1 U1.21 U6.6 U7.1 | length 783
  Top Layer w6: U1.21 703.94,599.21 730.22,625.49 730.22,734.6 818.38,822.76 R4.1 856.11,822.76 v1(866.53,833.18) 866.53,836.96 882.8,853.24 U6.6 ; U7.1 924.52,1091.59 934.55,1101.61 v1(934.55,1105.32)
  POWER w10: v1(866.53,833.18) 961.05,927.7 961.05,1078.82 v1(934.55,1105.32)
IIC2_SDA: R6.1 U1.22 U6.1 U7.16 | length 865.7
  Top Layer w6: U1.22 690.9,618.9 717.6,645.6 717.6,744.4 805.25,832.05 805.25,866.02 817.23,878 v1(838,878) 838,904.07 R6.1 ; v1(893.28,977) 893.28,1026 903.34,1036.06 903.34,1083.08 U7.16 ; v1(955,813.47) 991.07,813.47 1003.94,826.34 U6.1
  POWER w10: v1(838,878) 893.16,933.16 893.16,976.88 v1(893.28,977)
  Bottom Layer w6: v1(838,878) 890.47,878 v1(955,813.47)
key-2: U1.32 U2.4 | length 820
  Top Layer w8: v1(474,647) 479.63,652.63 U1.32
  POWER w8: v1(469,249) 471.73,251.73 471.73,383.94 459.59,396.08 459.59,631.11 474.74,646.26 v1(474,647) ; v1(525,244) 507.55,226.55 507.55,112.29 v1(594.24,25.6)
  Bottom Layer w8: v1(469,249) 474,244 v1(525,244) ; U2.4 562.61,35.43 569.44,28.6 591.24,28.6 v1(594.24,25.6)
KEY_1_WKUP: U1.10 U4.3 | length 492.9
  Top Layer w6: v1(381.04,165.5) 462.37,165.5 484.25,187.39 v1(557.7,187.39) ; U1.10 578.06,370.82 615,333.87 613,331.87 v1(613,323)
  POWER w8: v1@557.58,187.5 557.58,191.5 613,246.92 v1(613,323)
  Bottom Layer w6: v1@558.29,186.76 559.74,188.21 v1@558.29,188.21
  Bottom Layer w9: U4.3 383.17,162.94 v1@385.73,165.5
LCD_DC: L1.7 U1.45 | length 523.3
  Top Layer w8: v1(322.68,497.83) 325.84,497.83 328.8,500.79 U1.45
  POWER w8: v1(322.68,497.83) 288,532.51 288,670.83 317.11,699.94 317.11,744.29 v1(346.38,773.56)
  Bottom Layer w8: v1(346.38,773.56) 393.45,773.56 440.95,821.06 L1.7@440.95,863.95
LCD_RES: L1.11 U1.46 | length 786.6
  Top Layer w8: v1(303,474.77) 329.78,474.77 336.12,481.1 U1.46
  POWER w8: v1(303,474.77) 267.65,510.11 267.65,692.86 301.79,727 301.79,769.56 365.9,833.67 527.33,833.67 v1(568,793)
  Bottom Layer w6: L1.11@549.59,865.82 549.59,812.69 568,794.28 v1(568,793)
MPU_INT: R14.1 U1.41 U8.12 | length 332.3
  Top Layer w6: R14.1@141.72,653.06 R14.1 138.17,652.68 166.89,652.68 168.03,653.82 U8.12 ; v1(246.76,655.44) 322.68,579.53 U1.41
  Bottom Layer w6: v1(168.03,652.3) 243.62,652.3 v1(246.76,655.44)
NetAN1_1: AN1.1 BL2.1 | length 45.6
  Top Layer w19.68: AN1.1@216.09,1182.92 AN1.1@216.09,1187.53 ; AN1.1@221.01,1168.16 225.93,1163.24 BL2.1@259.97,1163.24
NetBC6_1: BC6.1 BC7.1 BL4.2 | length 59.1
  Top Layer w15.75: BC7.1 379.92,1055.63 BC6.1
NetBC7_2: BC7.2 BL3.2 BL5.1 | length 73.3
  Top Layer w15.75: BL3.2 317.67,1040.93 319.7,1042.97 322.49,1040.18 338.36,1040.18 ; BL5.1 349.18,1018.66 338.36,1029.48 338.36,1040.18 ; BC7.2 349.44,1051.26 338.36,1040.18
NetBC8_2: BC8.2 BL2.2 BL3.1 | length 89.4
  Top Layer w15: BL2.2@281.52,1141.69 278.73,1138.91 278.73,1138.38 284.1,1133.01 BC8.2 284.47,1097.74 284.47,1076.51 297.05,1063.94 297.05,1063.41 BL3.1
NetBC9_2: BC9.2 BC10.1 BL5.2 | length 60.6
  Top Layer w15.75: BL5.2 379.65,1013 BC10.1
NetC8_1: C8.1 pad.2@488,49.15 U2.6 | length 162.4
  Top Layer w10: v1(459.59,32.43) 482.17,32.43 488,38.25 488,49.15 C8.1
  Bottom Layer w10: v1(459.59,32.43) 481.98,32.43 487.81,38.25 U2.6
NetC10_1: C10.1 pad.2@553.81,48.22 U2.5 | length 127.8
  Top Layer w8: v1@525,25.6 546.98,25.6 553.81,32.43 553.81,48.22 553.18,48.86 553.18,127.47 C10.1
  other v1: 524.14,24.59
NetC14_1: C14.1 U8.20 | length 51.2
  Top Layer w8: C14.1 148.17,921.59 148.17,870.92 U8.20
NetC15_1: C15.1 U7.10 | length 157.1
  Top Layer w10: C15.1 v1(918.22,1214) ; U7.10 964.74,1162.29 964.74,1147.04 976.16,1135.62 v1(976.16,1133)
  Bottom Layer w10: v1(918.22,1214) 918.22,1200.9 976.16,1142.95 v1(976.16,1133)
NetC16_2: C16.2 U8.10 | length 89.8
  Top Layer w6: C16.2 83.66,653.19 100.52,653.19 125.75,678.42 125.75,710.36 U8.10
NetC17_1: C17.1 U7.8 | length 87.8
  Top Layer w8: C17.1 1016.19,1187.05 1016.19,1154.06 1004.73,1142.61 U7.8
NetC17_2: C17.2 U7.12 | length 77.7
  Top Layer w6: U7.12 924.52,1184.63 C17.2@953.89,1214 ; C17.2@953.89,1214 C17.2 954.83,1210.06 954.83,1213.06 C17.2@953.89,1214
NetC18_1: C18.1 U10.10 | length 56.8
  Top Layer w10: C18.1 918.22,666.68 924.47,660.42 U10.10
NetP0_1: P0.1 U5.3 | length 76.4
  Bottom Layer w8: P0.1 86.32,74 91.07,69.25 U5.3
NetP0_2: P0.2 U5.2 | length 76.7
  Bottom Layer w8: P0.2 53.65,48.65 122.54,48.65 U5.2
NetP2_1: P2.1 U9.2 | length 333.5
  Top Layer w10: v1(805.01,1168) 826.12,1168 850.01,1144.12 U9.2
  POWER w10: v1@788,902 788,1149.88 805.01,1166.88 v1(805.01,1168)
  other v1: 788,901
NetR8_1: R8.1 U5.1 | length 132.4
  Top Layer w8: v1@89.29,121.51 97,113.8 v1(97,22)
  Bottom Layer w8: v1(97,22) 104.64,22 112.49,29.85 U5.1
  other v1: 93.15,117.66
NetR12_2: R12.2 R13.1 U9.1 | length 113.8
  Top Layer w8: R13.1 841.09,1059.94 855.6,1074.44 U9.1
  Top Layer w10: R13.1 841.17,1055.93 841.17,997.07 R12.2
NetR15_2: R15.2 USB1.A5 | length 49.4
  Top Layer w6: v1(835.24,636.29) 846.78,636.29 847.07,636 849.65,638.58 R15.2
  Bottom Layer w6: USB1.A5 v1@826.71,636.29
NetR16_2: R16.2 USB1.B5 | length 69.2
  Top Layer w6: v1(836.25,530.47) 841.23,530.47 848.69,523 R16.2
  Bottom Layer w6: USB1.B5@791.59,518.95 825.6,518.95 836.25,529.6 v1(836.25,530.47)
NetR17_2: R17.2 U11.5 | length 59.3
  Top Layer w8: R17.2 839.4,275 853.73,289.33 U11.5
NetR18_2: R18.2 U12.1 | length 61.3
  Top Layer w18: R18.2 813.27,219.82 824.45,231 U12.1
NetT1_1: T1.1 U1.20 | length 124.5
  Top Layer w8: U1.20 707.78,579.53 T1.1
NetU2_3: U2.3 U4.1 | length 222.5
  Bottom Layer w8: U4.1@413.45,29.85 479.86,96.26 554.86,96.26 562.61,104.02 U2.3
NRST: R1.1 U1.7 | length 119.4
  Top Layer w6: U1.7 519,389.07 510.85,380.92 510.85,354.25 531.29,333.81 547.67,333.81 552.54,328.94 R1.1
P00: B1.19
P01: B1.18
P04: B1.15
P05: B1.14
P06: B1.13
P07: B1.12
P11: B1.9
P12: B1.8
P13: B1.7
P14: B1.6
P15: B1.5
P16: B1.38
P17: B1.37
P20: B1.36
P23: B1.33 BC11.1 X4.2 | length 145.3
  Top Layer w6: B1.33 587.71,915.18 587.71,872.07 608,851.78 X4.2@608,842.46 ; X4.2 X4.2@608,842.46 ; BC11.1 618.78,853.24 X4.2@608,842.46
P24: B1.32 BC14.1 X4.1 | length 142
  Top Layer w8: X4.1@548.94,844.28 548.94,851.78 570.64,873.47 B1.32
  Top Layer w10: BC14.1 540.17,853.06 548.94,844.28 X4.1
PC14: C1.2 U1.3 X1.2 | length 267.2
  Top Layer w6: C1.2 319.13,234.47 324,239.35 X1.2 324,342.14 334.08,352.22 394.15,352.22 440.26,398.33 U1.3
PC15: C2.2 U1.4 X1.1 | length 215
  Top Layer w6: C2.2 378.18,234.24 383.06,239.11 X1.1 383.06,314.99 459.94,391.88 U1.4
PH0: C3.1 U1.5 X2.1 | length 223.4
  Top Layer w6: C3.1 416.76,249.54 442.23,275 X2.1 450.24,275 472.3,297.06 472.3,330.59 479.63,337.92 U1.5
PH1: C4.2 U1.6 X2.3 | length 168.4
  Top Layer w6: U1.6 499.11,413.97 499.11,318.51 X2.3 508.13,309.5 515.49,309.5 516.75,308.24 549.87,275.12 C4.2
RBLAS: B1.30 BR1.1 | length 125.2
  Top Layer w8: BR1.1 408.24,918.06 412.11,921.94 436.22,921.94 454.51,940.23 483.45,940.23 490.49,947.26 B1.30
RESET: B1.20 SH1.3 | length 1202.2
  Top Layer w8: B1.20@551.53,1154.47 B1.20 550.95,1178.88 v1(567.78,1195.7)
  POWER w8: v1(567.78,1195.7) 567.78,824.04 633.86,757.96 633.86,617.36 684,567.22 v1(684,346)
  Bottom Layer w8: v1(684,346) 710.65,346 822.47,234.18 SH1.3
RF_N: B1.26 BC10.2 | length 53.2
  Top Layer w10: BC10.2@475.71,1013 475.71,1016.94 484.77,1026 B1.26
RF_P: B1.25 BC6.2 | length 52.1
  Top Layer w10: BC6.2@475.71,1056 475.71,1052.06 482.09,1045.68 B1.25
RXD: U1.31 U10.8 | length 679.6
  Top Layer w6: v1@487.27,723.3 v1(487.27,721.87) 499.12,710.02 499.12,686.02 U1.31 ; v1(752.06,674.76) 752.37,675.06 845.99,675.06 861.1,690.17 861.1,719.66 878.46,737.01 916.66,737.01 939.5,714.17 939.5,685.47 945.61,679.37 959.28,679.37 963.84,674.81 U10.8
  Bottom Layer w6: v1@487.27,723.3 504.81,740.84 531.72,740.84 558.29,714.26 628.04,714.26 642.71,728.93 697.89,728.93 v1(752.06,674.76)
SPI1_CS_FLASH: U1.14 U3.1 | length 579.3
  Top Layer w6: U1.14 677.04,461.42 687.96,450.5 687.96,426.66 678.3,417 661.37,417 v1(661.22,416.85)
  Top Layer w8: U3.1@212.79,472.52 212.79,468.29 219.66,461.42 219.66,463.65 244.53,463.65 v1(246.76,461.42)
  Bottom Layer w6: v1(246.76,461.42) 291.33,416.85 v1(661.22,416.85)
SPI1_CS_LCD: L1.8 U1.11 | length 649.9
  Top Layer w8: U1.11 597.74,390.79 615,373.53 v1(615,369)
  POWER w8: v1(447.91,795.01) 447.91,780.8 466.38,762.33 466.38,700.08 544.83,621.63 544.83,398.78 574.61,369 v1(615,369)
  Bottom Layer w8: v1(447.91,795.01) 466.99,814.09 L1.8@466.99,865.84
SPI1_MISO: R3.1 U1.16 U3.2 | length 617.4
  Top Layer w6: R3.1 v1(148,512) 148,497.83 162.79,483.04 U3.2 U3.2@162.79,472.52 ; v1(612.1,493.02) 615.8,493.02 622.83,500.05 644.25,500.05 U1.16
  Bottom Layer w6: v1(148,512) 196.05,560.05 531.98,560.05 599,493.02 v1(612.1,493.02)
SPI1_MOSI: L1.10 R5.1 U1.17 U3.5 | length 1512
  Top Layer w6: v1(611,520) 644.51,520 U1.17
  Top Layer w8: R5.1 43.95,535.9 40.08,532.02 40.08,188.21 62.79,165.5 U3.5 U3.5@62.79,154.98
  POWER w8: v1(539.92,788.65) 539.92,759.09 602.89,696.11 602.89,594.11 631.89,565.11 631.89,532.36 619.53,520 v1(611,520)
  Bottom Layer w6: v1(43,527) 43,534.13 115.76,606.89 132.24,606.89 162.02,577.11 544.24,577.11
  Bottom Layer w8: L1.10 522.03,807.78 539.92,789.89 v1(539.92,788.65) ; 544.24,577.11 601.35,520 v1(611,520)
SPI1_SCK: L1.9 R9.1 U1.15 U3.6 | length 1472.5
  Top Layer w6: U3.6@112.79,154.98 U3.6 112.79,189.99 132.27,209.47 212.6,209.47 246.52,243.39 246.52,382.4 187.46,441.46 187.46,531.02 192.34,535.9 R9.1 ; v1(578.06,452.01) 603.09,452.01 632.19,481.1 U1.15
  POWER w8: v1(508.84,791.42) 508.84,766.05 561.11,713.78 561.11,636.89 566.89,631.11 566.89,466.95 566.89,463.17 v1(578.06,452.01)
  Bottom Layer w6: v1(186,512) 203.6,529.6 461.33,529.6 538.92,452.01 v1(578.06,452.01) ; L1.9@494.93,865.84 494.93,805.34 v1(508.84,791.42)
ST25DV_GPO: R7.2 U1.28 U5.7 | length 1588.6
  Top Layer w6: U1.28 558.37,722.96 569.56,734.15 v1(597.67,734.15)
  POWER w8: v1(126.49,116.07) 270.07,116.07 v1(299.86,145.86) 322.68,168.68 322.68,206.32 v1(274,255) ; v1(597.67,734.15) 599.14,734.15 619.53,713.75 619.53,604.36 651.54,572.35 651.54,457.83 633.86,440.15 633.86,405.46 663.11,376.21 663.11,347.89 650,334.78 v1(650,323)
  Bottom Layer w6: U5.7 263.9,49.55 282.11,67.76 282.11,128.11 v1(299.86,145.86)
  Bottom Layer w8: R7.2@124,126 126.49,123.51 R7.2 ; v1(274,255) 238.54,290.46 238.54,363.59 271.68,396.73 278.06,396.73 279.87,398.54 532.68,398.54 583.11,348.11 617.43,348.11 630.43,335.11 634.73,335.11 646.84,323 v1(650,323)
SWCLK: SH1.4 U1.37 | length 1621.8
  Top Layer w6: U1.37 367.18,664.42 367.18,725.42 409.69,767.93 v1(431.24,767.93)
  POWER w10: v1(799.79,129) 799.79,115.69 811.47,104.02 828.13,104.02 934.59,210.48 934.59,511.63 982.89,559.93 982.89,660.35 918.22,725.03 v1(918.22,770.83)
  Bottom Layer w6: v1(431.24,767.93) 715.96,767.93 760.75,812.73 903,812.73 918.22,797.51 v1(918.22,770.83)
  Bottom Layer w8: v1(799.79,129) 799.79,142.34 852.27,194.81 SH1.4
SWDIO: SH1.5 U1.34 | length 1293.5
  Top Layer w6: U1.34 v1(440.26,724.26)
  POWER w10: v1(827,140) 903.16,216.16 903.16,545.74 918.22,560.8 918.22,694.44 894.76,717.9 v1(894.76,792.84)
  Bottom Layer w6: v1(440.26,724.26) 473.16,757.16 728.8,757.16 764.47,792.84 v1(894.76,792.84)
  Bottom Layer w8: v1(827,140) 828.03,140 843.47,155.44 SH1.5
SYS_ON: R24.2 U1.26 U15.6 | length 884.7
  Top Layer w8: U15.6 374.55,104.2 385.57,93.17 R24.2 ; v1(500.59,635.79) 501.82,634.55 568.02,634.55 569.4,633.17 573.28,633.17 573.35,633.11 590.65,633.11 602.89,645.35 602.89,662.65 597.74,667.8 U1.26
  POWER w8: v1(330.34,104.02) 368.42,142.09 445.38,142.09 489.89,186.6 489.89,625.08 v1(500.59,635.79)
SYS_WKUP2: B1.11 U1.2 | length 1582.9
  Top Layer w6: v1(365.75,1230.56) 368,1232.81 681.6,1232.81 699.96,1214.45 699.96,1195.7
  Top Layer w8: v1(246.76,412.91) 259.44,400.24 259.44,367.18 271.68,354.95 288.98,354.95 306.15,372.11 391.31,372.11 420.57,401.38 U1.2 ; 699.96,1195.7 712.09,1183.57 722.69,1183.57 728.12,1178.15 B1.11
  POWER w10: v1(246.76,412.91) 274,440.15 274,467.83 219.89,521.94 219.89,526.04 219,526.93 219,673.09 258.12,712.21 258.12,733.73 258.12,755.16 328.09,825.13 328.09,1192.9 v1(365.75,1230.56)
TIM1_CH1: L1.2 U1.29 | length 431.1
  Top Layer w6: v1@280.33,742.79 303,765.46 v1(303,833.18) ; U1.29 538.68,657.32 v1(540,656)
  Bottom Layer w6: v1(280.01,742.79) 283.71,742.79 292.55,733.95 292.55,725.9 318.11,700.34 318.11,699.76 329.76,688.11 330.34,688.11 350.55,667.9 520.78,667.9 532.69,656 v1(540,656)
TIM2_CH1: R12.1 U1.38 | length 1051.8
  Top Layer w6: v1(237,972) 322.89,886.11 322.89,745.13 311,733.24 311,676.92 349.33,638.58 U1.38 ; v1(810.62,977) 810.76,977.14 R12.1
  Bottom Layer w6: v1(237,972) 245.89,972 301.89,1028 639.14,1028 690.14,977 v1(810.62,977)
TXD: U1.30 U10.9 | length 563.4
  Top Layer w6: v1@515.03,723.3 519.74,718.59 519.74,686.56 U1.30 ; v1(750.11,645.5) 751.19,645.5 763.08,657.39 891.01,657.39 902.9,645.5 902.9,632.72 915.67,619.96 944.15,619.96 U10.9
  Bottom Layer w6: v1@515.03,723.3 522,723.3 545.54,699.76 631.9,699.76 641.23,709.1 674.21,709.1 677.81,705.5 ; v1@745.12,645.5 v1(750.11,645.5)
  Bottom Layer w8: 677.81,705.5 737.81,645.5 v1@745.12,645.5
  other v1: 517.38,720.95
USART2_RX: B1.16 U1.13 | length 1045.7
  Top Layer w6: U1.13 639.23,435.98 639.23,407.11 649.38,396.96 755.75,396.96 v1(757.33,398.54)
  Top Layer w8: B1.16 630.27,1154.47 630.27,1191.04 v1(631.9,1192.66)
  POWER w8: v1(631.9,1192.66) 631.9,868.36 728,772.26 728,606.46 757.33,577.13 v1(757.33,398.54)
USART2_TX: B1.17 U1.12 | length 1052.4
  Top Layer w6: U1.12 617.43,400.63 642.17,375.89 702.8,375.89 v1(707.39,371.3)
  Top Layer w8: v1(600.17,1193.67) 600.17,1190.51 609.43,1181.24 609.43,1154.47 B1.17
  POWER w8: v1(600.17,1193.67) 600.17,924.57 585.2,909.6 585.2,838.63 675.64,748.19 675.64,668.23 659.14,651.73 659.14,620.2 707.39,571.95 v1(707.39,371.3)
usb_in_sign: R21.2 R22.1 U1.39 | length 615.4
  Top Layer w6: v1@341.47,617.51 342.41,618.45 372.88,618.45 U1.39 ; v1(752,612) 837.12,612 R22.1 849.9,595.28 875.5,569.68 875.5,564.72 R21.2
  Bottom Layer w6: v1(340,618) 362,596 736,596 v1(752,612)
USB_M/SDA: B1.3
USB_P/SCL: B1.2
V_EH: R8.2 U1.27 | length 1091.6
  Top Layer w8: U1.27 582,681.88 v1(582,654)
  POWER w6: v1(28.95,149.64) 65.01,185.7 v1(65.01,592.94)
  Bottom Layer w6: v1@33.92,143.29 42.4,134.81 55.67,134.81 60.55,129.94 R8.2 ; v1(65.01,592.94) 97.82,625.74 292.45,625.74 304.6,637.89 363.65,637.89 389.54,612 532.69,612 540.82,620.14 541.04,620.14 574.96,654.06 575.03,654 v1(582,654)
VBAT: C21.2 P3.1 U11.3 U12.4 U12.5 U13.1 U13.3 | length 846.8
  Top Layer w23.62: U13.3 630.68,129.09 663.26,129.09 677.24,143.06 677.24,189.07 663.4,202.91 U13.1 ; U11.3 1002.35,364.14 1016.19,350.3 1016.19,207.44 1002.35,193.6 v1(984.5,193.6) U12.5 U12.4
  POWER w23.62: v1(690.14,89.24) 723.37,56 903.16,56 1002.45,155.29 1002.45,169.94 v1(1016.19,156.2)
  other v1: 659.14,89.24 615,126 651.54,126 989.7,154.98 1016.19,193.6
VCC1: B1.4 B1.10 B1.21 B1.24 B1.27 B1.28 B1.29 B1.31 B1.39 BC1.1 BC2.1 BC3.1 BC4.1 BC5.1 BL1.1 | length 1408.7
  Top Layer w10: BC3.1 409.11,825.87 409.11,844.28 418.06,853.24 ; BC5.1 406.24,865.06 418.06,853.24 ; BC2.1 476.54,1113.51 493.08,1113.51 498.27,1118.7 498.27,1120.07 506.81,1128.61 v1(506.81,1131.23) ; B1.27 B1.28 ; B1.24 v1(544.83,1065.37) 555,1055.2 555,997 544.63,986.63 B1.28 ; BC4.1 B1.39 708.43,944.77 726.86,963.2 726.86,1000.14 v1(732.84,1006.12) ; B1.10 v1(757.33,1169.21) BC1.1 ; 418.06,853.24 BL1.1 445.24,894.85 468.18,917.8 B1.31 550.95,958.31 542.52,966.75 521.43,966.75 B1.29 B1.28
  POWER w19.68: v1(544.83,1065.37) 531.42,1065.37 502.96,1093.83 502.96,1206.96 521.2,1225.2 701.34,1225.2 v1(757.33,1169.21) 757.33,1030.61 v1(732.84,1006.12)
VDD-BLE: BL1.2 U14.1 | length 1267.2
  Top Layer w10: v1(351,744.85) 365.68,744.85 428.92,808.08 430.03,808.08 438.84,816.9 439.37,816.9 BL1.2
  Top Layer w15: v1(414.82,189.62) 418.8,193.6 463,193.6 485.54,216.14 582.1,216.14 588.11,210.13 588.11,114.86 654.75,48.22 699.53,48.22 751.71,100.4 U14.1@807.24,100.4 ; U14.1 798.68,99.39 U14.1@799.5,100.22
  POWER w15: v1(351,744.85) 364.39,731.46 364.39,240.06 v1(414.82,189.62)
VDD-MCU: C5.2 C6.2 C7.2 C22.1 R1.2 SH1.6 U1.1 U1.9 U1.24 U1.36 U1.48 U2.1 U4.2 U13.5 U14.4 U14.5 U15.4 U15.5 | length 2241.2
  Top Layer w8: U1.36 400.89,699.12 389.22,710.79 389.22,731.91 402.46,745.15 553.18,745.15 563.07,755.04 616.54,755.04 657.52,714.06 668.67,714.06 687.96,694.78 C5.2 ; 413.27,452.01 545.95,452.01 558.37,439.58 U1.9
  Top Layer w10: U15.5 U15.4 346.38,29.39 ; C6.2 332.24,416.85 357.05,441.65 U1.48 U1.48 403,441.73 ; 347.06,34.2 C7.2 ; U1.1 400.89,439.62 403,441.73 ; U1.36 400.97,685.75 400.97,661.8 413.27,649.5 413.27,452.01 403,441.73 ; U1.9 558.37,364.49 580.72,342.14 580.72,327.29 R1.2 583.01,321.06 614.74,289.33 649.84,289.33 677.24,261.94 C22.1 677.24,254.06 709.5,221.8 709.5,208.73 U13.5@715.32,202.91 ; U1.24@644.91,658.19 U1.24 657.62,658.27 657.7,658.35 657.7,659.68 658.82,659.68 687.96,688.81 C5.2@687.96,690.04
  Top Layer w20: U14.4 U14.5
  Bottom Layer w8: v1(303,69.2) v1@303,69.43 ; U4.2 345.57,57.02 357.32,68.77 374.71,68.77 396.79,90.85 420.57,90.85 456.75,127.03 480.98,127.03 487.81,133.85 U2.1
  Bottom Layer w20: U2.1 488.64,147.48 488.64,176.86 526.88,215.1 692.8,215.1 v1(739.14,168.77) 739.14,141.59 786.42,94.31 826.09,94.31 832.85,101.07 ; v1(849.85,25.6) 832.85,42.6 832.85,101.07 ; SH1.6 880.15,116.07 878.34,117.88 849.66,117.88 832.85,101.07
  other v1: 301.32,25.6 902.9,25.6 717.6,193.6
XOC_1: B1.22 BC13.2 X3.3 | length 201.9
  Top Layer w8: X3.3 BC13.2 509.16,1166.34 548.94,1126.55 548.94,1109.43 544.83,1105.32 521.81,1105.32 B1.22
XOC_2: B1.23 BC12.1 X3.1 | length 225.7
  Top Layer w8: BC12.1@350.61,1168 400.19,1168 X3.1 404.85,1170.69 413.66,1161.88 413.66,1159.91 440.51,1133.07 440.51,1103.51 458.96,1085.06 B1.23
pads on no net: M1.3 SH1.8 SH1.9 U1.19 U5.9 U6.3 U6.4 U7.3 U7.5 U7.6 U7.7 U7.14 U8.2 U8.3 U8.4 U8.5 U8.14 U8.15 U8.16 U8.17 U8.19 U8.21 U8.22 U10.4 U10.5 U10.6 U11.1 U12.3 U13.4 U14.3 U15.3 USB1. USB1.1 USB1.2 USB1.3 USB1.4 USB1.A8 USB1.B8

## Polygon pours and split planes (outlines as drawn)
GND on GND "Top Layer-No Net1" (solid, pour order 6): 0,0 0,1259.84 1043.31,1259.84 1043.31,0
GND on Bottom Layer "Top Layer-No Net3" (solid, pour order 8): 0,0 0,1259.84 1043.31,1259.84 1043.31,0
GND on POWER "Top Layer-No Net2" (solid, pour order 7): 0,0 0,1259.84 1043.31,1259.84 1043.31,0
GND on Top Layer "Top Layer-No Net" (solid, pour order 5): 0,0 0,1259.84 1043.31,1259.84 1043.31,0

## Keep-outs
Keep-Out Layer:
  the board outline again, w10

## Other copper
Top Layer:
  rectangle net VDD-MCU: 286.03,17 346.38,74
  rectangle net VDD-MCU: 707.78,153 751.44,211.4
  rectangle net VDD-MCU: 849.85,25.6 902.9,71.6
  rectangle net VBAT: 966.64,145 1029,193.6
  pour cut-out: 274,1259.16 273.53,1258.69 273.53,1007.16 0,1007.16 0,1259
GND:
  pour cut-out: 274,1260 273.53,1259.53 273.53,1008 0,1008 0,1259.84
POWER:
  rectangle net VBAT: 593.81,74 698.52,135
  rectangle net VBAT: 966.64,145 1029,203
  pour cut-out: 274,1260 273.53,1259.53 273.53,1008 0,1008 0,1259.84
Bottom Layer:
  region net VDD-MCU: 345.57,17.76 345.57,75.76 301.32,75.76 301.32,17.76
  rectangle net VBAT: 594.24,89.24 667.53,112.54
  region net VDD-MCU: 900.9,17 900.9,44.69 834.9,44.69 834.9,17
  rectangle net VDD-MCU: 831.78,17 915.67,40
  pour cut-out: 274,1260 273.53,1259.53 273.53,1008 0,1008 0,1259.84

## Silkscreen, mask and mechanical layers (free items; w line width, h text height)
Top Overlay:
  lines w10: 5.45,100.52 1032.47,100.52
Bottom Overlay:
  text "TH-watch V2.4" at 533.24,1133 h39.37
  text "TXH 21.5.24" at 440.95,1066.19 h39.37
  text "DD" at 821,311 h60
  text "TH-watch V2.4" at 487,308 h60
  text "DC" at 821,268 h60
  text "TXH 21.5.24" at 452,238 h60
  text "RS" at 821,225 h60
  text "SC" at 819,176 h60
  text "SD" at 821,131.65 h60
  text "VDD" at 849,82.72 h60
  text "GND" at 849,33 h60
